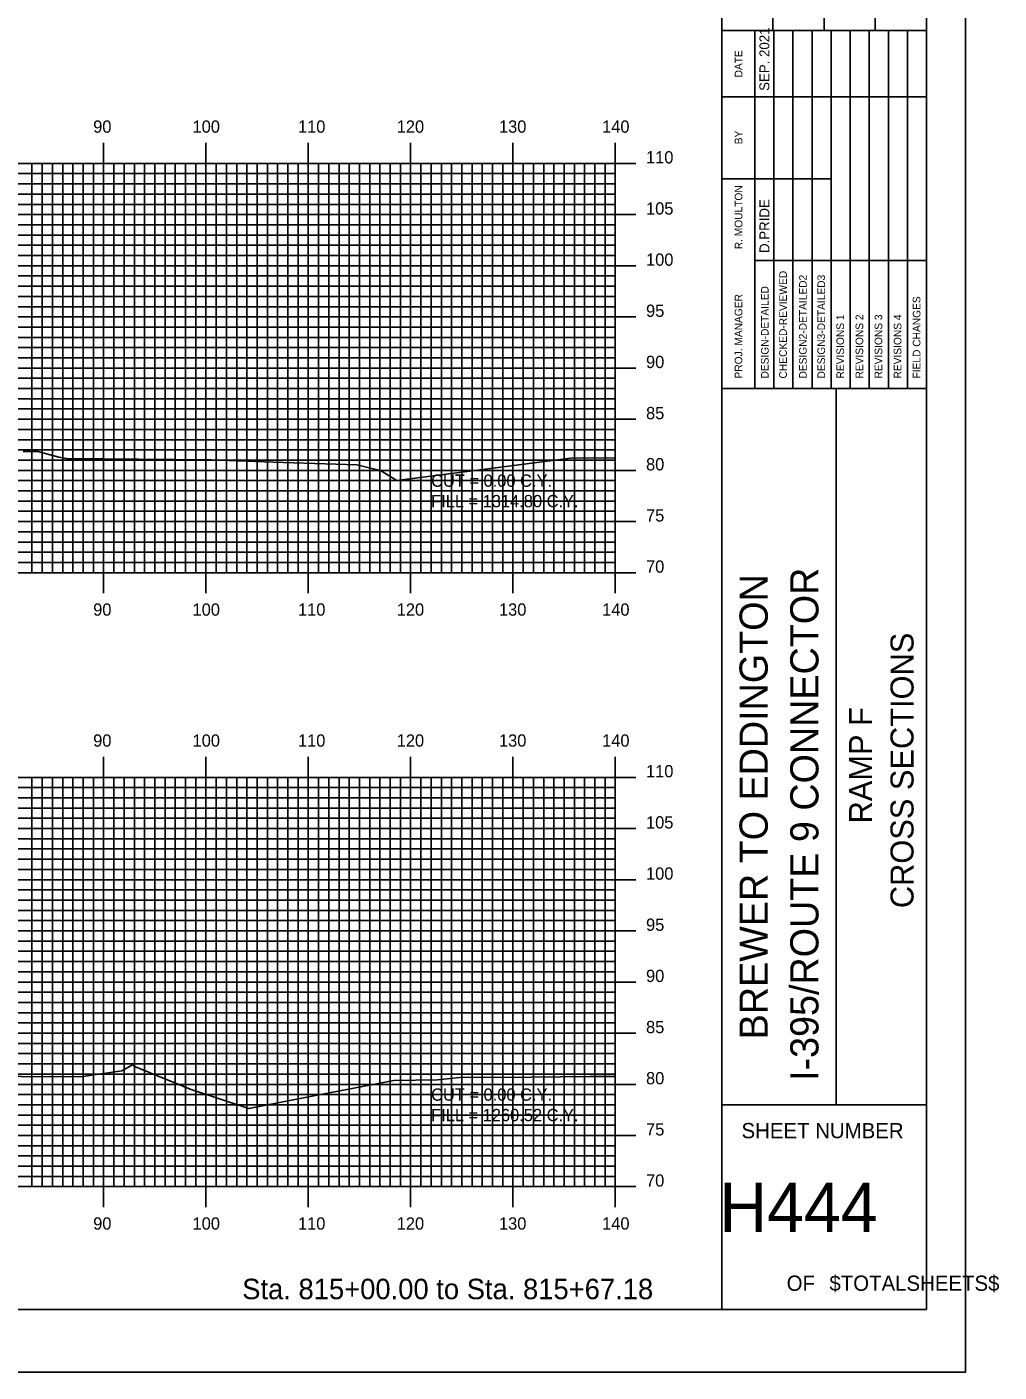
# Model space of a CAD drawing. Extents: x 2846 to 3190, y -1658 to -1438.
# Drawn here: x 3094.7 to 3189.7, y -1657.7 to -1526.3 of the extents above; entities that cross this region are included whole.
import ezdxf

# ---------------------------------------------------------------- set-up
doc = ezdxf.new("R2010")
doc.units = 0
for name, color, linetype in [('BORDER', 7, 'Continuous'), ('D_Text_Standard', 7, 'Continuous'), ('H_V ANNOTATION', 7, 'Continuous'), ('MAJOR', 7, 'Continuous'), ('MINOR', 7, 'Continuous'), ('PLOT BOUNDARY', 7, 'Continuous'), ('S_Roadway_Centerline', 7, 'Continuous')]:
    doc.layers.add(name, color=color, linetype=linetype)

msp = doc.modelspace()

# ---------------------------------------------------------------- linework, layer by layer
at = {"layer": 'BORDER'}
for p, q in [((3162.61, -1651.6), (3162.61, -1441.6)), ((3167.61, -1526.6), (3167.61, -1509.3)), ((3172.61, -1526.6), (3172.61, -1509.3)), ((3177.61, -1526.6), (3177.61, -1509.3)), ((3162.61, -1526.6), (3182.61, -1526.6)), ((3162.61, -1561.6), (3182.61, -1561.6)), ((3173.79, -1631.6), (3173.79, -1561.6)), ((3162.61, -1631.6), (3182.61, -1631.6))]:
    msp.add_line(p, q, dxfattribs=at)
msp.add_lwpolyline([(2862.61, -1651.6), (3182.61, -1651.6), (3182.61, -1441.6), (2862.61, -1441.6)], close=True, dxfattribs=at)
for points in [[(3165.84, -1533.1), (3165.84, -1526.6)], [(3167.71, -1561.59), (3167.71, -1526.6)], [(3169.57, -1526.6), (3169.57, -1561.59)], [(3171.43, -1561.59), (3171.43, -1526.6)], [(3173.3, -1561.59), (3173.3, -1526.6)], [(3175.16, -1561.59), (3175.16, -1526.6)], [(3177.02, -1561.59), (3177.02, -1526.6)], [(3178.89, -1561.59), (3178.89, -1526.6)], [(3180.75, -1561.59), (3180.75, -1526.6)], [(3165.84, -1561.59), (3165.84, -1528.01)], [(3162.61, -1533.1), (3182.61, -1533.1)], [(3162.61, -1541.1), (3165.84, -1541.1)], [(3165.84, -1541.1), (3173.3, -1541.1)], [(3165.84, -1549.1), (3182.61, -1549.1)]]:
    msp.add_lwpolyline(points, dxfattribs=at)
at = {"layer": 'MAJOR'}
for p, q in [((3102.21, -1537.6), (3102.21, -1539.6)), ((3112.21, -1537.6), (3112.21, -1539.6)), ((3122.21, -1537.6), (3122.21, -1539.6)), ((3132.21, -1537.6), (3132.21, -1539.6)), ((3142.21, -1537.6), (3142.21, -1539.6)), ((3152.21, -1537.6), (3152.21, -1539.6)), ((2872.21, -1539.6), (3152.21, -1539.6)), ((2872.21, -1539.6), (3152.21, -1539.6)), ((3102.21, -1579.6), (3102.21, -1539.6)), ((3112.21, -1579.6), (3112.21, -1539.6)), ((3122.21, -1579.6), (3122.21, -1539.6)), ((3132.21, -1579.6), (3132.21, -1539.6)), ((3142.21, -1579.6), (3142.21, -1539.6)), ((3154.22, -1539.6), (3150.21, -1539.6)), ((3152.21, -1579.6), (3152.21, -1539.6)), ((3152.21, -1579.6), (3152.21, -1539.6)), ((2872.21, -1544.6), (3152.21, -1544.6)), ((3154.22, -1544.6), (3150.21, -1544.6)), ((2872.21, -1549.6), (3152.21, -1549.6)), ((3154.22, -1549.6), (3150.21, -1549.6)), ((2872.21, -1554.6), (3152.21, -1554.6)), ((3154.22, -1554.6), (3150.21, -1554.6)), ((2872.21, -1559.6), (3152.21, -1559.6)), ((3154.22, -1559.6), (3150.21, -1559.6)), ((2872.21, -1564.6), (3152.21, -1564.6)), ((3154.22, -1564.6), (3150.21, -1564.6)), ((2872.21, -1569.6), (3152.21, -1569.6)), ((3154.22, -1569.6), (3150.21, -1569.6)), ((2872.21, -1574.6), (3152.21, -1574.6)), ((3154.22, -1574.6), (3150.21, -1574.6)), ((2872.21, -1579.6), (3152.21, -1579.6)), ((2872.21, -1579.6), (3152.21, -1579.6)), ((3102.21, -1581.61), (3102.21, -1579.6)), ((3112.21, -1581.61), (3112.21, -1579.6)), ((3122.21, -1581.61), (3122.21, -1579.6)), ((3132.21, -1581.61), (3132.21, -1579.6)), ((3142.21, -1581.61), (3142.21, -1579.6)), ((3154.22, -1579.6), (3150.21, -1579.6)), ((3152.21, -1581.61), (3152.21, -1579.6)), ((3102.21, -1597.6), (3102.21, -1599.6)), ((3112.21, -1597.6), (3112.21, -1599.6)), ((3122.21, -1597.6), (3122.21, -1599.6)), ((3132.21, -1597.6), (3132.21, -1599.6)), ((3142.21, -1597.6), (3142.21, -1599.6)), ((3152.21, -1597.6), (3152.21, -1599.6)), ((2872.21, -1599.6), (3152.21, -1599.6)), ((2872.21, -1599.6), (3152.21, -1599.6)), ((3102.21, -1639.6), (3102.21, -1599.6)), ((3112.21, -1639.6), (3112.21, -1599.6)), ((3122.21, -1639.6), (3122.21, -1599.6)), ((3132.21, -1639.6), (3132.21, -1599.6)), ((3142.21, -1639.6), (3142.21, -1599.6)), ((3154.22, -1599.6), (3150.21, -1599.6)), ((3152.21, -1639.6), (3152.21, -1599.6)), ((3152.21, -1639.6), (3152.21, -1599.6)), ((2872.21, -1604.6), (3152.21, -1604.6)), ((3154.22, -1604.6), (3150.21, -1604.6)), ((2872.21, -1609.6), (3152.21, -1609.6)), ((3154.22, -1609.6), (3150.21, -1609.6)), ((2872.21, -1614.6), (3152.21, -1614.6)), ((3154.22, -1614.6), (3150.21, -1614.6)), ((2872.21, -1619.6), (3152.21, -1619.6)), ((3154.22, -1619.6), (3150.21, -1619.6)), ((2872.21, -1624.6), (3152.21, -1624.6)), ((3154.22, -1624.6), (3150.21, -1624.6)), ((2872.21, -1629.6), (3152.21, -1629.6)), ((3154.22, -1629.6), (3150.21, -1629.6)), ((2872.21, -1634.6), (3152.21, -1634.6)), ((3154.22, -1634.6), (3150.21, -1634.6)), ((2872.21, -1639.6), (3152.21, -1639.6)), ((2872.21, -1639.6), (3152.21, -1639.6)), ((3102.21, -1641.61), (3102.21, -1639.6)), ((3112.21, -1641.61), (3112.21, -1639.6)), ((3122.21, -1641.61), (3122.21, -1639.6)), ((3132.21, -1641.61), (3132.21, -1639.6)), ((3142.21, -1641.61), (3142.21, -1639.6)), ((3154.22, -1639.6), (3150.21, -1639.6)), ((3152.21, -1641.61), (3152.21, -1639.6))]:
    msp.add_line(p, q, dxfattribs=at)
at = {"layer": 'MINOR'}
for p, q in [((2872.21, -1540.6), (3152.21, -1540.6)), ((3095.21, -1579.6), (3095.21, -1539.6)), ((3096.21, -1579.6), (3096.21, -1539.6)), ((3097.21, -1579.6), (3097.21, -1539.6)), ((3098.21, -1579.6), (3098.21, -1539.6)), ((3099.21, -1579.6), (3099.21, -1539.6)), ((3100.21, -1579.6), (3100.21, -1539.6)), ((3101.21, -1579.6), (3101.21, -1539.6)), ((3103.21, -1579.6), (3103.21, -1539.6)), ((3104.21, -1579.6), (3104.21, -1539.6)), ((3105.21, -1579.6), (3105.21, -1539.6)), ((3106.21, -1579.6), (3106.21, -1539.6)), ((3107.21, -1579.6), (3107.21, -1539.6)), ((3108.21, -1579.6), (3108.21, -1539.6)), ((3109.21, -1579.6), (3109.21, -1539.6)), ((3110.21, -1579.6), (3110.21, -1539.6)), ((3111.21, -1579.6), (3111.21, -1539.6)), ((3113.21, -1579.6), (3113.21, -1539.6)), ((3114.21, -1579.6), (3114.21, -1539.6)), ((3115.21, -1579.6), (3115.21, -1539.6)), ((3116.21, -1579.6), (3116.21, -1539.6)), ((3117.21, -1579.6), (3117.21, -1539.6)), ((3118.21, -1579.6), (3118.21, -1539.6)), ((3119.21, -1579.6), (3119.21, -1539.6)), ((3120.21, -1579.6), (3120.21, -1539.6)), ((3121.21, -1579.6), (3121.21, -1539.6)), ((3123.21, -1579.6), (3123.21, -1539.6)), ((3124.21, -1579.6), (3124.21, -1539.6)), ((3125.21, -1579.6), (3125.21, -1539.6)), ((3126.21, -1579.6), (3126.21, -1539.6)), ((3127.21, -1579.6), (3127.21, -1539.6)), ((3128.21, -1579.6), (3128.21, -1539.6)), ((3129.21, -1579.6), (3129.21, -1539.6)), ((3130.21, -1579.6), (3130.21, -1539.6)), ((3131.21, -1579.6), (3131.21, -1539.6)), ((3133.21, -1579.6), (3133.21, -1539.6)), ((3134.21, -1579.6), (3134.21, -1539.6)), ((3135.21, -1579.6), (3135.21, -1539.6)), ((3136.21, -1579.6), (3136.21, -1539.6)), ((3137.21, -1579.6), (3137.21, -1539.6)), ((3138.21, -1579.6), (3138.21, -1539.6)), ((3139.21, -1579.6), (3139.21, -1539.6)), ((3140.21, -1579.6), (3140.21, -1539.6)), ((3141.21, -1579.6), (3141.21, -1539.6)), ((3143.21, -1579.6), (3143.21, -1539.6)), ((3144.21, -1579.6), (3144.21, -1539.6)), ((3145.21, -1579.6), (3145.21, -1539.6)), ((3146.21, -1579.6), (3146.21, -1539.6)), ((3147.21, -1579.6), (3147.21, -1539.6)), ((3148.21, -1579.6), (3148.21, -1539.6)), ((3149.21, -1579.6), (3149.21, -1539.6)), ((3150.21, -1579.6), (3150.21, -1539.6)), ((3152.21, -1540.6), (3150.21, -1540.6)), ((3151.21, -1579.6), (3151.21, -1539.6)), ((2872.21, -1541.6), (3152.21, -1541.6)), ((3152.21, -1541.6), (3150.21, -1541.6)), ((2872.21, -1542.6), (3152.21, -1542.6)), ((3152.21, -1542.6), (3150.21, -1542.6)), ((2872.21, -1543.6), (3152.21, -1543.6)), ((3152.21, -1543.6), (3150.21, -1543.6)), ((2872.21, -1545.6), (3152.21, -1545.6)), ((3152.21, -1545.6), (3150.21, -1545.6)), ((2872.21, -1546.6), (3152.21, -1546.6)), ((3152.21, -1546.6), (3150.21, -1546.6)), ((2872.21, -1547.6), (3152.21, -1547.6)), ((2872.21, -1548.6), (3152.21, -1548.6)), ((3152.21, -1547.6), (3150.21, -1547.6)), ((3152.21, -1548.6), (3150.21, -1548.6)), ((2872.21, -1550.6), (3152.21, -1550.6)), ((3152.21, -1550.6), (3150.21, -1550.6)), ((2872.21, -1551.6), (3152.21, -1551.6)), ((3152.21, -1551.6), (3150.21, -1551.6)), ((2872.21, -1552.6), (3152.21, -1552.6)), ((2872.21, -1553.6), (3152.21, -1553.6)), ((3152.21, -1552.6), (3150.21, -1552.6)), ((3152.21, -1553.6), (3150.21, -1553.6)), ((2872.21, -1555.6), (3152.21, -1555.6)), ((3152.21, -1555.6), (3150.21, -1555.6)), ((2872.21, -1556.6), (3152.21, -1556.6)), ((2872.21, -1557.6), (3152.21, -1557.6)), ((3152.21, -1556.6), (3150.21, -1556.6)), ((3152.21, -1557.6), (3150.21, -1557.6)), ((2872.21, -1558.6), (3152.21, -1558.6)), ((3152.21, -1558.6), (3150.21, -1558.6)), ((2872.21, -1560.6), (3152.21, -1560.6)), ((2872.21, -1561.6), (3152.21, -1561.6)), ((3152.21, -1560.6), (3150.21, -1560.6)), ((3152.21, -1561.6), (3150.21, -1561.6)), ((2872.21, -1562.6), (3152.21, -1562.6)), ((3152.21, -1562.6), (3150.21, -1562.6)), ((2872.21, -1563.6), (3152.21, -1563.6)), ((3152.21, -1563.6), (3150.21, -1563.6)), ((2872.21, -1565.6), (3152.21, -1565.6)), ((3152.21, -1565.6), (3150.21, -1565.6)), ((2872.21, -1566.6), (3152.21, -1566.6)), ((3152.21, -1566.6), (3150.21, -1566.6)), ((2872.21, -1567.6), (3152.21, -1567.6)), ((3152.21, -1567.6), (3150.21, -1567.6)), ((2872.21, -1568.6), (3152.21, -1568.6)), ((3152.21, -1568.6), (3150.21, -1568.6)), ((2872.21, -1570.6), (3152.21, -1570.6)), ((3152.21, -1570.6), (3150.21, -1570.6)), ((2872.21, -1571.6), (3152.21, -1571.6)), ((3152.21, -1571.6), (3150.21, -1571.6)), ((2872.21, -1572.6), (3152.21, -1572.6)), ((2872.21, -1573.6), (3152.21, -1573.6)), ((3152.21, -1572.6), (3150.21, -1572.6)), ((3152.21, -1573.6), (3150.21, -1573.6)), ((2872.21, -1575.6), (3152.21, -1575.6)), ((3152.21, -1575.6), (3150.21, -1575.6)), ((2872.21, -1576.6), (3152.21, -1576.6)), ((3152.21, -1576.6), (3150.21, -1576.6)), ((2872.21, -1577.6), (3152.21, -1577.6)), ((2872.21, -1578.6), (3152.21, -1578.6)), ((3152.21, -1577.6), (3150.21, -1577.6)), ((3152.21, -1578.6), (3150.21, -1578.6)), ((3095.21, -1639.6), (3095.21, -1599.6)), ((3096.21, -1639.6), (3096.21, -1599.6)), ((3097.21, -1639.6), (3097.21, -1599.6)), ((3098.21, -1639.6), (3098.21, -1599.6)), ((3099.21, -1639.6), (3099.21, -1599.6)), ((3100.21, -1639.6), (3100.21, -1599.6)), ((3101.21, -1639.6), (3101.21, -1599.6)), ((3103.21, -1639.6), (3103.21, -1599.6)), ((3104.21, -1639.6), (3104.21, -1599.6)), ((3105.21, -1639.6), (3105.21, -1599.6)), ((3106.21, -1639.6), (3106.21, -1599.6)), ((3107.21, -1639.6), (3107.21, -1599.6)), ((3108.21, -1639.6), (3108.21, -1599.6)), ((3109.21, -1639.6), (3109.21, -1599.6)), ((3110.21, -1639.6), (3110.21, -1599.6)), ((3111.21, -1639.6), (3111.21, -1599.6)), ((3113.21, -1639.6), (3113.21, -1599.6)), ((3114.21, -1639.6), (3114.21, -1599.6)), ((3115.21, -1639.6), (3115.21, -1599.6)), ((3116.21, -1639.6), (3116.21, -1599.6)), ((3117.21, -1639.6), (3117.21, -1599.6)), ((3118.21, -1639.6), (3118.21, -1599.6)), ((3119.21, -1639.6), (3119.21, -1599.6)), ((3120.21, -1639.6), (3120.21, -1599.6)), ((3121.21, -1639.6), (3121.21, -1599.6)), ((3123.21, -1639.6), (3123.21, -1599.6)), ((3124.21, -1639.6), (3124.21, -1599.6)), ((3125.21, -1639.6), (3125.21, -1599.6)), ((3126.21, -1639.6), (3126.21, -1599.6)), ((3127.21, -1639.6), (3127.21, -1599.6)), ((3128.21, -1639.6), (3128.21, -1599.6)), ((3129.21, -1639.6), (3129.21, -1599.6)), ((3130.21, -1639.6), (3130.21, -1599.6)), ((3131.21, -1639.6), (3131.21, -1599.6)), ((3133.21, -1639.6), (3133.21, -1599.6)), ((3134.21, -1639.6), (3134.21, -1599.6)), ((3135.21, -1639.6), (3135.21, -1599.6)), ((3136.21, -1639.6), (3136.21, -1599.6)), ((3137.21, -1639.6), (3137.21, -1599.6)), ((3138.21, -1639.6), (3138.21, -1599.6)), ((3139.21, -1639.6), (3139.21, -1599.6)), ((3140.21, -1639.6), (3140.21, -1599.6)), ((3141.21, -1639.6), (3141.21, -1599.6)), ((3143.21, -1639.6), (3143.21, -1599.6)), ((3144.21, -1639.6), (3144.21, -1599.6)), ((3145.21, -1639.6), (3145.21, -1599.6)), ((3146.21, -1639.6), (3146.21, -1599.6)), ((3147.21, -1639.6), (3147.21, -1599.6)), ((3148.21, -1639.6), (3148.21, -1599.6)), ((3149.21, -1639.6), (3149.21, -1599.6)), ((3150.21, -1639.6), (3150.21, -1599.6)), ((3151.21, -1639.6), (3151.21, -1599.6)), ((2872.21, -1600.6), (3152.21, -1600.6)), ((3152.21, -1600.6), (3150.21, -1600.6)), ((2872.21, -1601.6), (3152.21, -1601.6)), ((3152.21, -1601.6), (3150.21, -1601.6)), ((2872.21, -1602.6), (3152.21, -1602.6)), ((2872.21, -1603.6), (3152.21, -1603.6)), ((3152.21, -1602.6), (3150.21, -1602.6)), ((3152.21, -1603.6), (3150.21, -1603.6)), ((2872.21, -1605.6), (3152.21, -1605.6)), ((3152.21, -1605.6), (3150.21, -1605.6)), ((2872.21, -1606.6), (3152.21, -1606.6)), ((2872.21, -1607.6), (3152.21, -1607.6)), ((3152.21, -1606.6), (3150.21, -1606.6)), ((3152.21, -1607.6), (3150.21, -1607.6)), ((2872.21, -1608.6), (3152.21, -1608.6)), ((3152.21, -1608.6), (3150.21, -1608.6)), ((2872.21, -1610.6), (3152.21, -1610.6)), ((2872.21, -1611.6), (3152.21, -1611.6)), ((3152.21, -1610.6), (3150.21, -1610.6)), ((3152.21, -1611.6), (3150.21, -1611.6)), ((2872.21, -1612.6), (3152.21, -1612.6)), ((3152.21, -1612.6), (3150.21, -1612.6)), ((2872.21, -1613.6), (3152.21, -1613.6)), ((3152.21, -1613.6), (3150.21, -1613.6)), ((2872.21, -1615.6), (3152.21, -1615.6)), ((3152.21, -1615.6), (3150.21, -1615.6)), ((2872.21, -1616.6), (3152.21, -1616.6)), ((3152.21, -1616.6), (3150.21, -1616.6)), ((2872.21, -1617.6), (3152.21, -1617.6)), ((3152.21, -1617.6), (3150.21, -1617.6)), ((2872.21, -1618.6), (3152.21, -1618.6)), ((3152.21, -1618.6), (3150.21, -1618.6)), ((2872.21, -1620.6), (3152.21, -1620.6)), ((3152.21, -1620.6), (3150.21, -1620.6)), ((2872.21, -1621.6), (3152.21, -1621.6)), ((3152.21, -1621.6), (3150.21, -1621.6)), ((2872.21, -1622.6), (3152.21, -1622.6)), ((3152.21, -1622.6), (3150.21, -1622.6)), ((2872.21, -1623.6), (3152.21, -1623.6)), ((3152.21, -1623.6), (3150.21, -1623.6)), ((2872.21, -1625.6), (3152.21, -1625.6)), ((3152.21, -1625.6), (3150.21, -1625.6)), ((2872.21, -1626.6), (3152.21, -1626.6)), ((3152.21, -1626.6), (3150.21, -1626.6)), ((2872.21, -1627.6), (3152.21, -1627.6)), ((2872.21, -1628.6), (3152.21, -1628.6)), ((3152.21, -1627.6), (3150.21, -1627.6)), ((3152.21, -1628.6), (3150.21, -1628.6)), ((2872.21, -1630.6), (3152.21, -1630.6)), ((3152.21, -1630.6), (3150.21, -1630.6)), ((2872.21, -1631.6), (3152.21, -1631.6)), ((2872.21, -1632.6), (3152.21, -1632.6)), ((3152.21, -1631.6), (3150.21, -1631.6)), ((3152.21, -1632.6), (3150.21, -1632.6)), ((2872.21, -1633.6), (3152.21, -1633.6)), ((3152.21, -1633.6), (3150.21, -1633.6)), ((2872.21, -1635.6), (3152.21, -1635.6)), ((2872.21, -1636.6), (3152.21, -1636.6)), ((3152.21, -1635.6), (3150.21, -1635.6)), ((3152.21, -1636.6), (3150.21, -1636.6)), ((2872.21, -1637.6), (3152.21, -1637.6)), ((3152.21, -1637.6), (3150.21, -1637.6)), ((2872.21, -1638.6), (3152.21, -1638.6)), ((3152.21, -1638.6), (3150.21, -1638.6))]:
    msp.add_line(p, q, dxfattribs=at)
at = {"layer": 'PLOT BOUNDARY'}
msp.add_lwpolyline([(2846.43, -1657.72), (3186.43, -1657.72), (3186.43, -1437.72), (2846.43, -1437.72)], close=True, dxfattribs=at)
at = {"layer": 'S_Roadway_Centerline'}
for points in [[(3094.36, -1567.77), (3095.78, -1567.74), (3097.82, -1568.3), (3098.57, -1568.43), (3112.71, -1568.58), (3118.74, -1568.81), (3126.95, -1569.07), (3129.27, -1569.61), (3130.87, -1570.59), (3137.99, -1569.69), (3147.82, -1568.39), (3152.21, -1568.37)], [(3082.53, -1628.76), (3099.94, -1628.88), (3103.98, -1628.29), (3105.04, -1627.69), (3105.17, -1627.82), (3110.67, -1630.06), (3116.41, -1631.95), (3122.07, -1630.84), (3130.57, -1629.22), (3134.83, -1629.15), (3137.03, -1628.94), (3143.99, -1628.91), (3149.71, -1628.83), (3152.21, -1628.82)]]:
    msp.add_lwpolyline(points, dxfattribs=at)

# ---------------------------------------------------------------- texts
at = {"layer": 'BORDER'}
for s, height, p in [('SEP. 2021', 0.969, (3167.26, -1532.51)), ('DATE', 0.743, (3164.62, -1531.19)), ('BY', 0.743, (3164.62, -1537.73)), ('R. MOULTON', 0.745, (3164.62, -1547.99)), ('D.PRIDE', 0.969, (3167.26, -1548.35)), ('CHECKED-REVIEWED', 0.7455, (3168.97, -1560.62)), ('DESIGN2-DETAILED2', 0.7455, (3170.91, -1560.62)), ('DESIGN3-DETAILED3', 0.7455, (3172.7, -1560.62)), ('PROJ. MANAGER', 0.7455, (3164.62, -1560.62)), ('DESIGN-DETAILED', 0.7455, (3167.19, -1560.62)), ('FIELD CHANGES', 0.7455, (3182.02, -1560.62)), ('REVISIONS 1', 0.7455, (3174.56, -1560.62)), ('REVISIONS 2', 0.7455, (3176.43, -1560.62)), ('REVISIONS 3', 0.7455, (3178.29, -1560.62)), ('REVISIONS 4', 0.7455, (3180.16, -1560.62)), ('BREWER TO EDDINGTON', 2.7557, (3167.1, -1625.2)), ('I-395/ROUTE 9 CONNECTOR', 2.7557, (3172.06, -1629.27)), ('CROSS SECTIONS', 2.25, (3181.35, -1612.38)), ('RAMP F', 2.25, (3177.3, -1604.1))]:
    msp.add_text(s, height=height, rotation=90, dxfattribs=at).set_placement(p)
for s, height, p in [('SHEET NUMBER', 1.4905, (3164.54, -1634.87)), ('H444', 4.839, (3162.37, -1644.04)), ('OF', 1.491, (3168.95, -1649.78)), ('$TOTALSHEETS$', 1.4905, (3173.13, -1649.78))]:
    msp.add_text(s, height=height, dxfattribs=at).set_placement(p)
at = {"layer": 'D_Text_Standard'}
for s, p in [('CUT = 0.00 C.Y.', (3134.21, -1571.2)), ('FILL = 1314.80 C.Y.', (3134.21, -1573.2)), ('CUT = 0.00 C.Y.', (3134.21, -1631.2)), ('FILL = 1260.52 C.Y.', (3134.21, -1633.2))]:
    msp.add_text(s, height=1.2, dxfattribs=at).set_placement(p)
at = {"layer": 'H_V ANNOTATION'}
for s, height, p in [('90', 1.2, (3101.19, -1536.6)), ('100', 1.2, (3110.9, -1536.6)), ('110', 1.2, (3121.2, -1536.6)), ('120', 1.2, (3130.85, -1536.6)), ('130', 1.2, (3140.84, -1536.6)), ('140', 1.2, (3150.92, -1536.6)), ('110', 1.2, (3155.21, -1539.6)), ('105', 1.2, (3155.21, -1544.6)), ('100', 1.2, (3155.21, -1549.6)), ('95', 1.2, (3155.21, -1554.6)), ('90', 1.2, (3155.21, -1559.6)), ('85', 1.2, (3155.21, -1564.6)), ('80', 1.2, (3155.21, -1569.6)), ('75', 1.2, (3155.21, -1574.6)), ('70', 1.2, (3155.21, -1579.6)), ('90', 1.2, (3101.19, -1583.8)), ('100', 1.2, (3110.9, -1583.8)), ('110', 1.2, (3121.2, -1583.8)), ('120', 1.2, (3130.85, -1583.8)), ('130', 1.2, (3140.84, -1583.8)), ('140', 1.2, (3150.92, -1583.8)), ('90', 1.2, (3101.19, -1596.6)), ('100', 1.2, (3110.9, -1596.6)), ('110', 1.2, (3121.2, -1596.6)), ('120', 1.2, (3130.85, -1596.6)), ('130', 1.2, (3140.84, -1596.6)), ('140', 1.2, (3150.92, -1596.6)), ('110', 1.2, (3155.21, -1599.6)), ('105', 1.2, (3155.21, -1604.6)), ('100', 1.2, (3155.21, -1609.6)), ('95', 1.2, (3155.21, -1614.6)), ('90', 1.2, (3155.21, -1619.6)), ('85', 1.2, (3155.21, -1624.6)), ('80', 1.2, (3155.21, -1629.6)), ('75', 1.2, (3155.21, -1634.6)), ('70', 1.2, (3155.21, -1639.6)), ('90', 1.2, (3101.19, -1643.8)), ('100', 1.2, (3110.9, -1643.8)), ('110', 1.2, (3121.2, -1643.8)), ('120', 1.2, (3130.85, -1643.8)), ('130', 1.2, (3140.84, -1643.8)), ('140', 1.2, (3150.92, -1643.8)), ('Sta. 815+00.00 to Sta. 815+67.18', 2.0004, (3115.75, -1650.6))]:
    msp.add_text(s, height=height, dxfattribs=at).set_placement(p)

doc.saveas('drawing.dxf')
